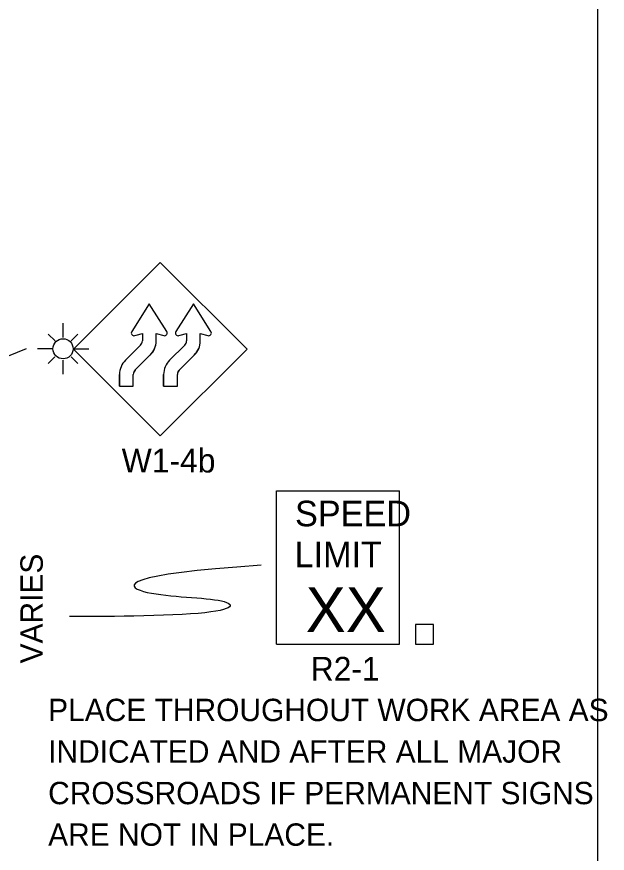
# Model space of a CAD drawing. Extents: x 16723 to 18475, y 7015 to 8267.
# Drawn here: x 17241 to 17425.7, y 7769.1 to 8030.8 of the extents above; entities that cross this region are included whole.
import ezdxf

# ---------------------------------------------------------------- set-up
doc = ezdxf.new("R2010")
doc.units = 0
for name, color, linetype in [('BORDER', 7, 'Continuous'), ('TRAFFIC_SIGNS_PR', 7, 'Continuous'), ('TYPICAL_TEXT_DIMEN_PR', 7, 'Continuous')]:
    doc.layers.add(name, color=color, linetype=linetype)

msp = doc.modelspace()

# ---------------------------------------------------------------- linework, layer by layer
at = {"layer": 'BORDER'}
msp.add_line((17422.75, 7216.25), (17422.75, 8216.25), dxfattribs=at)
at = {"layer": 'TRAFFIC_SIGNS_PR'}
for p, q in [((17285.9, 7953.97), (17258.75, 7926.82)), ((17313.06, 7926.82), (17285.9, 7953.97)), ((17255.51, 7930.48), (17255.51, 7934.99)), ((17253, 7929.44), (17250.89, 7931.55)), ((17258.02, 7929.44), (17260.13, 7931.55)), ((17252.35, 7926.93), (17247.52, 7926.93)), ((17258.66, 7926.93), (17263.54, 7926.93)), ((17258.75, 7926.82), (17285.9, 7899.66)), ((17275.04, 7923.35), (17279.75, 7928.06)), ((17279.75, 7928.06), (17275.04, 7923.35)), ((17285.9, 7899.66), (17313.06, 7926.82)), ((17288.83, 7923.35), (17293.55, 7928.06)), ((17293.55, 7928.06), (17288.83, 7923.35)), ((17252.99, 7924.42), (17250.89, 7922.31)), ((17258.02, 7924.42), (17260.13, 7922.31)), ((17278.09, 7920.3), (17282.8, 7925.01)), ((17278.09, 7920.3), (17282.8, 7925.01)), ((17291.88, 7920.3), (17296.6, 7925.01)), ((17291.89, 7920.3), (17296.6, 7925.01)), ((17255.51, 7918.96), (17255.51, 7923.37)), ((17273.17, 7915.23), (17273.17, 7918.93)), ((17277.49, 7915.23), (17277.49, 7918.93)), ((17286.97, 7915.23), (17286.97, 7918.93)), ((17291.28, 7915.23), (17291.28, 7918.93)), ((17273.17, 7915.23), (17277.49, 7915.23)), ((17286.97, 7915.23), (17291.28, 7915.23)), ((17322.3, 7882.53), (17360.7, 7882.53)), ((17322.3, 7834.53), (17322.3, 7882.53)), ((17360.7, 7834.53), (17360.7, 7882.53)), ((17322.3, 7834.53), (17360.7, 7834.53))]:
    msp.add_line(p, q, dxfattribs=at)
for points in [[(17287.96, 7932.34), (17282.47, 7940.95), (17276.99, 7932.34)], [(17287.96, 7932.34), (17282.47, 7940.95), (17276.99, 7932.34)], [(17301.75, 7932.34), (17296.27, 7940.95), (17290.79, 7932.34)], [(17301.75, 7932.34), (17296.27, 7940.95), (17290.79, 7932.34)], [(17277.95, 7931.04), (17280.31, 7931.69), (17280.31, 7929.4)], [(17277.95, 7931.04), (17278.79, 7931.27), (17280.31, 7931.69), (17280.31, 7929.4)], [(17284.63, 7929.32), (17284.63, 7931.69), (17286.99, 7931.04)], [(17284.63, 7929.32), (17284.63, 7931.69), (17286.99, 7931.04)], [(17291.75, 7931.04), (17294.11, 7931.69), (17294.11, 7929.4)], [(17291.75, 7931.04), (17292.58, 7931.27), (17294.11, 7931.69), (17294.11, 7929.4)], [(17298.42, 7929.32), (17298.43, 7931.69), (17300.79, 7931.04)], [(17298.42, 7929.32), (17298.43, 7931.69), (17300.79, 7931.04)], [(17273.17, 7918.93), (17273.17, 7915.23), (17277.49, 7915.23), (17277.49, 7918.93)], [(17286.97, 7918.93), (17286.97, 7915.23), (17291.28, 7915.23), (17291.28, 7918.93)]]:
    msp.add_lwpolyline(points, dxfattribs=at)
msp.add_lwpolyline([(17365.71, 7834.53), (17371.31, 7834.53), (17371.31, 7840.7), (17365.71, 7840.7)], close=True, dxfattribs=at)
msp.add_circle((17255.51, 7926.93), 3.15, dxfattribs=at)
for centre, radius, start, end in [((17277.72, 7931.88), 0.864, 147.5204, 285.3986), ((17277.72, 7931.88), 0.866, 147.5288, 285.3852), ((17287.22, 7931.88), 0.866, 254.6799, 32.2804), ((17287.22, 7931.88), 0.866, 254.6828, 32.2708), ((17297.07, 7938.14), 10.8, 212.4569, 212.4665), ((17291.52, 7931.88), 0.864, 147.5204, 285.3986), ((17291.52, 7931.88), 0.866, 147.5288, 285.3852), ((17301.02, 7931.88), 0.866, 254.6828, 32.2708), ((17301.02, 7931.88), 0.866, 254.6799, 32.2804), ((17310.86, 7938.14), 10.8, 212.4569, 212.4665), ((17278.46, 7929.39), 1.85, 314.2123, 0.1238), ((17278.46, 7929.39), 1.85, 314.2125, 0), ((17278.46, 7929.39), 6.17, 314.2125, 359.3819), ((17278.46, 7929.39), 6.17, 314.7687, 359.3755), ((17284.14, 7920.62), 10.8, 74.68, 74.6808), ((17292.26, 7929.39), 1.85, 314.2123, 0.1238), ((17292.26, 7929.39), 1.85, 314.2125, 0), ((17292.26, 7929.39), 6.17, 314.2125, 359.3819), ((17292.26, 7929.39), 6.17, 314.7687, 359.3755), ((17297.94, 7920.62), 10.8, 74.68, 74.6808), ((17279.34, 7918.93), 6.17, 134.2125, 180), ((17279.34, 7918.93), 6.17, 134.2125, 180), ((17279.34, 7918.93), 6.17, 134.2117, 180), ((17293.13, 7918.93), 6.17, 134.2125, 180), ((17293.13, 7918.93), 6.17, 134.2125, 180), ((17293.13, 7918.93), 6.17, 134.2117, 180), ((17279.34, 7918.93), 1.85, 132.372, 180), ((17279.34, 7918.93), 1.85, 134.2125, 180), ((17293.13, 7918.93), 1.85, 132.372, 180), ((17293.13, 7918.93), 1.85, 134.2125, 180)]:
    msp.add_arc(centre, radius, start, end, dxfattribs=at)
at = {"layer": 'TYPICAL_TEXT_DIMEN_PR'}
msp.add_line((17244.02, 7926.93), (17222.03, 7918), dxfattribs=at)
msp.add_open_spline([(17317.52, 7859.19), (17273.94, 7856.28), (17275.22, 7849.27), (17309.82, 7849.27), (17309.82, 7843.12), (17261.52, 7843.12), (17257.58, 7843.12)], degree=3, dxfattribs=at)

# ---------------------------------------------------------------- texts
at = {"layer": 'TRAFFIC_SIGNS_PR'}
for s, height, p in [('W1-4b', 7.44, (17273.86, 7888.22)), ('SPEED', 8, (17328.06, 7871.39)), ('LIMIT', 8, (17327.9, 7858.59)), ('XX', 14.031, (17331.41, 7838.29)), ('R2-1', 7.44, (17332.97, 7823.09)), ('PLACE THROUGHOUT WORK AREA AS', 7, (17250.85, 7810.42)), ('INDICATED AND AFTER ALL MAJOR', 7, (17250.85, 7797.42)), ('CROSSROADS IF PERMANENT SIGNS', 7, (17250.85, 7784.42)), ('ARE NOT IN PLACE.', 7, (17250.85, 7771.42))]:
    msp.add_text(s, height=height, dxfattribs=at).set_placement(p)
at = {"layer": 'TYPICAL_TEXT_DIMEN_PR'}
msp.add_text('VARIES', height=7, rotation=90, dxfattribs=at).set_placement((17249.18, 7828.48))

doc.saveas('drawing.dxf')
